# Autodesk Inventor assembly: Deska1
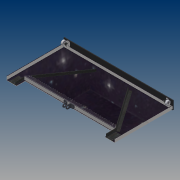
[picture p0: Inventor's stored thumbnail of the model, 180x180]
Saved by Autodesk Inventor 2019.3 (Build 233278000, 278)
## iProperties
Created: 2019-02
Part Number: Deska1
Material: Všeobecné
Document SubType Name: Assembly
Designer: B-hon
Author: B-hon
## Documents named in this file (11)
- C:\Users\B-hon\OneDrive\Plocha\Bakalářka22\Deska horní\Deska1.iam
- C:\Users\B-hon\OneDrive\Plocha\Bakalářka22\Deska horní\Výztuha1.ipt
- C:\Users\B-hon\OneDrive\Plocha\Bakalářka22\Deska horní\Výztuha2.ipt
- C:\Users\B-hon\OneDrive\Plocha\Bakalářka22\Rolna leva.iam
- C:\Users\B-hon\OneDrive\Plocha\Bakalářka22\Rolna prava.iam
- C:\Users\B-hon\OneDrive\Plocha\Bakalářka22\Deska horní\Plech desky.ipt
- C:\Users\B-hon\OneDrive\Plocha\Bakalářka22\Deska horní\Lišta1.ipt
- C:\Users\B-hon\OneDrive\Plocha\Bakalářka22\Deska střední\CSN 426935 - 25x25x2-580.ipt
- C:\Users\B-hon\OneDrive\Plocha\Bakalářka22\Deska střední\Držák ojnice.ipt
- C:\Users\B-hon\OneDrive\Documents\Inventor\Content Center Files\R2019\cs-CZ\DIN 7991(2)\DIN 7991 - M5x8.ipt
- C:\Users\B-hon\OneDrive\Documents\Inventor\Content Center Files\R2019\cs-CZ\CNS 4558\CNS 4558 - M5 x 0,8 x 8.ipt
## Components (26 placed, 10 different names)
1. Výztuha1:1 — Vložit:1, Vložit:4, Proti sobě:2
2. Výztuha2:1 — Vložit:2, Vložit:3
3. Plech desky:1 — Vložit:1, Vložit:2, Vložit:3, Vložit:4, Vložit:5, Vložit:6, Proti sobě:1, Stejný směr:1
4. Lišta1:1 — Vložit:5, Vložit:6, Vložit:7, Vložit:8, Vložit:9, Vložit:10
5. Rolna leva:1 [sub-assembly] — Vložit:7, Vložit:8
6. Rolna prava:1 [sub-assembly] — Vložit:9, Vložit:10
7. CSN 426935 - 25x25x2-580:1 — Proti sobě:1, Stejný směr:1, Proti sobě:2, Vložit:11, Vložit:12, Stejný směr:2, Stejný směr:3
8. Držák ojnice:1 — Vložit:11, Stejný směr:3
9. Držák ojnice:2 — Vložit:12, Stejný směr:2
10. DIN 7991 M5x8:5
11. DIN 7991 M5x8:6
12. DIN 7991 M5x8:7
13. DIN 7991 M5x8:8
14. CNS 4558 M5 x 8:3
15. CNS 4558 M5 x 8:8
16. CNS 4558 M5 x 8:9
17. DIN 7991 M5x8:1
18. DIN 7991 M5x8:2
19. DIN 7991 M5x8:3
20. DIN 7991 M5x8:4
21. CNS 4558 M5 x 8:1
22. CNS 4558 M5 x 8:2
23. CNS 4558 M5 x 8:4
24. CNS 4558 M5 x 8:5
25. CNS 4558 M5 x 8:6
26. CNS 4558 M5 x 8:7
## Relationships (17: Insert 12, Flush 3, Mate 2)
- Vložit:1 [Insert]: Výztuha1:1 ↔ Plech desky:1
- Vložit:2 [Insert]: Výztuha2:1 ↔ Plech desky:1
- Vložit:3 [Insert]: Výztuha2:1 ↔ Plech desky:1
- Vložit:4 [Insert]: Výztuha1:1 ↔ Plech desky:1
- Vložit:5 [Insert]: Plech desky:1 ↔ Lišta1:1
- Vložit:6 [Insert]: Plech desky:1 ↔ Lišta1:1
- Vložit:7 [Insert]: Lišta1:1 ↔ Rolna leva:1
- Vložit:8 [Insert]: Lišta1:1 ↔ Rolna leva:1
- Vložit:9 [Insert]: Lišta1:1 ↔ Rolna prava:1
- Vložit:10 [Insert]: Lišta1:1 ↔ Rolna prava:1
- Proti sobě:1 [Mate]: Plech desky:1 ↔ CSN 426935 - 25x25x2-580:1
- Stejný směr:1 [Flush]: Plech desky:1 ↔ CSN 426935 - 25x25x2-580:1
- Proti sobě:2 [Mate]: Výztuha1:1 ↔ CSN 426935 - 25x25x2-580:1
- Vložit:11 [Insert]: CSN 426935 - 25x25x2-580:1 ↔ Držák ojnice:1
- Vložit:12 [Insert]: CSN 426935 - 25x25x2-580:1 ↔ Držák ojnice:2
- Stejný směr:2 [Flush]: CSN 426935 - 25x25x2-580:1 ↔ Držák ojnice:2
- Stejný směr:3 [Flush]: CSN 426935 - 25x25x2-580:1 ↔ Držák ojnice:1
